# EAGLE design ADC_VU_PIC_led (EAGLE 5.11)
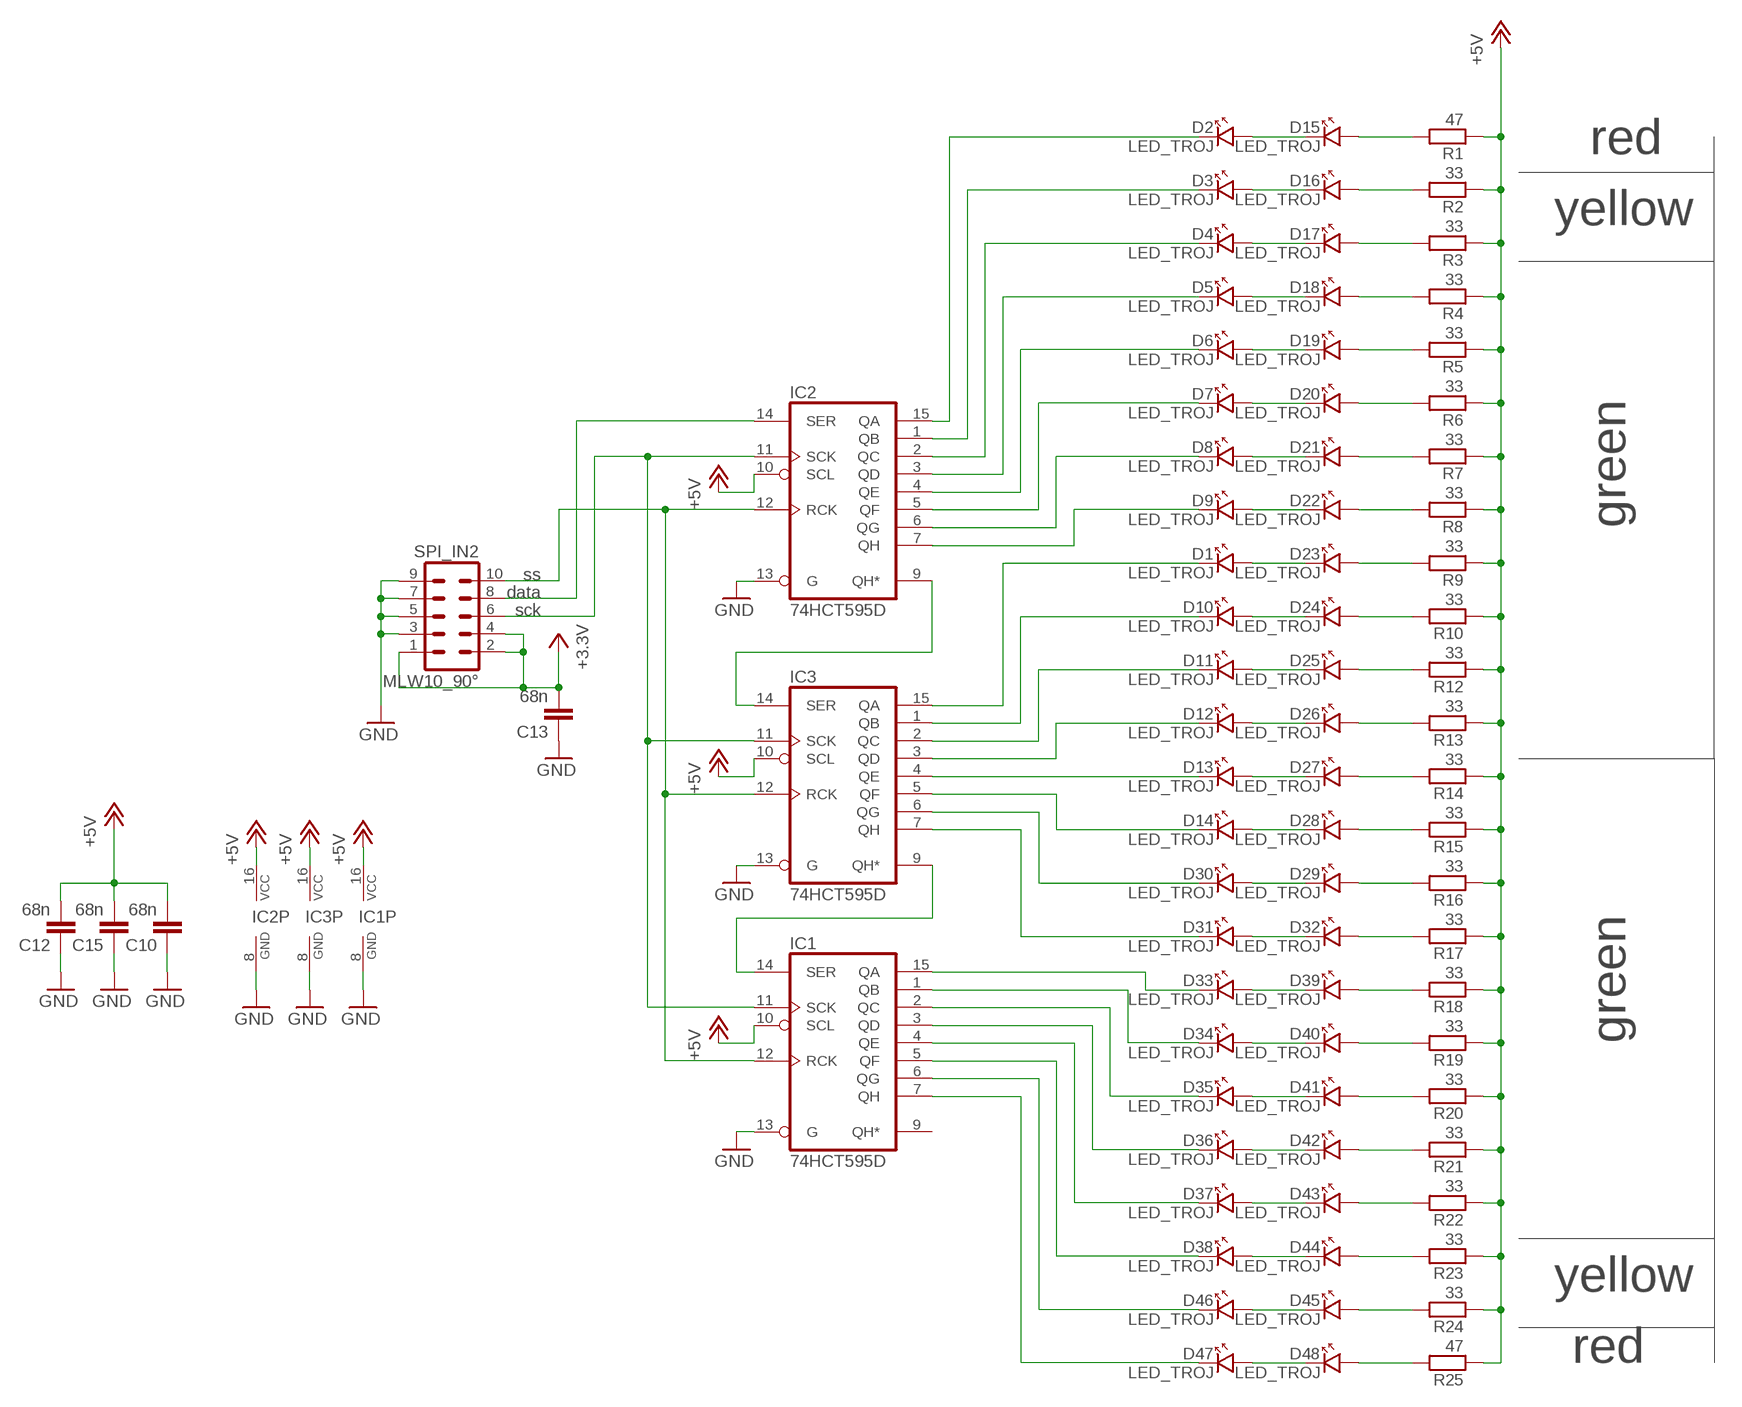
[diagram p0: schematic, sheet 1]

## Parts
C10  68n  C-EUC1206  [C1206]
C12  68n  C-EUC1206  [C1206]
C13  68n  C-EUC1206  [C1206]
C15  68n  C-EUC1206  [C1206]
D1  LED_TROJ  [LED_TROJ]
D2  LED_TROJ  [LED_TROJ]
D3  LED_TROJ  [LED_TROJ]
D4  LED_TROJ  [LED_TROJ]
D5  LED_TROJ  [LED_TROJ]
D6  LED_TROJ  [LED_TROJ]
D7  LED_TROJ  [LED_TROJ]
D8  LED_TROJ  [LED_TROJ]
D9  LED_TROJ  [LED_TROJ]
D10  LED_TROJ  [LED_TROJ]
D11  LED_TROJ  [LED_TROJ]
D12  LED_TROJ  [LED_TROJ]
D13  LED_TROJ  [LED_TROJ]
D14  LED_TROJ  [LED_TROJ]
D15  LED_TROJ  [LED_TROJ]
D16  LED_TROJ  [LED_TROJ]
D17  LED_TROJ  [LED_TROJ]
D18  LED_TROJ  [LED_TROJ]
D19  LED_TROJ  [LED_TROJ]
D20  LED_TROJ  [LED_TROJ]
D21  LED_TROJ  [LED_TROJ]
D22  LED_TROJ  [LED_TROJ]
D23  LED_TROJ  [LED_TROJ]
D24  LED_TROJ  [LED_TROJ]
D25  LED_TROJ  [LED_TROJ]
D26  LED_TROJ  [LED_TROJ]
D27  LED_TROJ  [LED_TROJ]
D28  LED_TROJ  [LED_TROJ]
D29  LED_TROJ  [LED_TROJ]
D30  LED_TROJ  [LED_TROJ]
D31  LED_TROJ  [LED_TROJ]
D32  LED_TROJ  [LED_TROJ]
D33  LED_TROJ  [LED_TROJ]
D34  LED_TROJ  [LED_TROJ]
D35  LED_TROJ  [LED_TROJ]
D36  LED_TROJ  [LED_TROJ]
D37  LED_TROJ  [LED_TROJ]
D38  LED_TROJ  [LED_TROJ]
D39  LED_TROJ  [LED_TROJ]
D40  LED_TROJ  [LED_TROJ]
D41  LED_TROJ  [LED_TROJ]
D42  LED_TROJ  [LED_TROJ]
D43  LED_TROJ  [LED_TROJ]
D44  LED_TROJ  [LED_TROJ]
D45  LED_TROJ  [LED_TROJ]
D46  LED_TROJ  [LED_TROJ]
D47  LED_TROJ  [LED_TROJ]
D48  LED_TROJ  [LED_TROJ]
IC1  74HCT595D  [SO16]
IC2  74HCT595D  [SO16]
IC3  74HCT595D  [SO16]
R1  47  R_SMD_0805  [0805]
R2  33  R_SMD_0805  [0805]
R3  33  R_SMD_0805  [0805]
R4  33  R_SMD_0805  [0805]
R5  33  R_SMD_0805  [0805]
R6  33  R_SMD_0805  [0805]
R7  33  R_SMD_0805  [0805]
R8  33  R_SMD_0805  [0805]
R9  33  R_SMD_0805  [0805]
R10  33  R_SMD_0805  [0805]
R12  33  R_SMD_0805  [0805]
R13  33  R_SMD_0805  [0805]
R14  33  R_SMD_0805  [0805]
R15  33  R_SMD_0805  [0805]
R16  33  R_SMD_0805  [0805]
R17  33  R_SMD_0805  [0805]
R18  33  R_SMD_0805  [0805]
R19  33  R_SMD_0805  [0805]
R20  33  R_SMD_0805  [0805]
R21  33  R_SMD_0805  [0805]
R22  33  R_SMD_0805  [0805]
R23  33  R_SMD_0805  [0805]
R24  33  R_SMD_0805  [0805]
R25  47  R_SMD_0805  [0805]
SPI_IN2  MLW10_90°  [MLW10A]

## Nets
+12V: C10.2 C12.2 C15.2 IC1.10(SCL) IC1.16(VCC) IC2.10(SCL) IC2.16(VCC) IC3.10(SCL) IC3.16(VCC) R1.1 R2.1 R3.1 R4.1 R5.1 R6.1 R7.1 R8.1 R9.1 R10.1 R12.1 R13.1 R14.1 R15.1 R16.1 R17.1 R18.1 R19.1 R20.1 R21.1 R22.1 R23.1 R24.1 R25.1 ; supply symbol labelled +5V
GND: C10.1 C12.1 C13.1 C15.1 IC1.8(GND) IC1.13(G) IC2.8(GND) IC2.13(G) IC3.8(GND) IC3.13(G) SPI_IN2.3 SPI_IN2.5 SPI_IN2.7 SPI_IN2.9
N$1: IC1.14(SER) IC3.9(QH*)
N$2: D31.K IC3.7(QH)
N$3: D2.A D15.K
N$4: D3.A D16.K
N$5: D4.A D17.K
N$6: D5.A D18.K
N$7: D6.A D19.K
N$8: D7.A D20.K
N$9: D8.A D21.K
N$10: D9.A D22.K
N$11: D33.K IC1.15(QA)
N$12: D46.K IC1.6(QG)
N$13: D34.K IC1.1(QB)
N$14: D1.A D23.K
N$15: D35.K IC1.2(QC)
N$16: IC1.11(SCK) IC2.11(SCK) IC3.11(SCK) SPI_IN2.6
N$17: D36.K IC1.3(QD)
N$18: D37.K IC1.4(QE)
N$19: D38.K IC1.5(QF)
N$20: D2.K IC2.15(QA)
N$21: D3.K IC2.1(QB)
N$22: D9.K IC2.7(QH)
N$23: D10.A D24.K
N$24: D11.A D25.K
N$25: D12.A D26.K
N$26: D13.A D27.K
N$27: D14.A D28.K
N$28: D29.K D30.A
N$29: D31.A D32.K
N$30: D33.A D39.K
N$31: D34.A D40.K
N$32: D35.A D41.K
N$33: D36.A D42.K
N$34: D37.A D43.K
N$35: D38.A D44.K
N$36: D4.K IC2.2(QC)
N$37: D5.K IC2.3(QD)
N$38: D8.K IC2.6(QG)
N$39: D7.K IC2.5(QF)
N$40: D6.K IC2.4(QE)
N$41: D45.K D46.A
N$42: D1.K IC3.15(QA)
N$43: D30.K IC3.6(QG)
N$44: D10.K IC3.1(QB)
N$45: D11.K IC3.2(QC)
N$46: D12.K IC3.3(QD)
N$47: D47.A D48.K
N$48: D14.K IC3.5(QF)
N$49: D47.K IC1.7(QH)
N$50: IC2.14(SER) SPI_IN2.8
N$51: D15.A R1.2
N$52: IC2.9(QH*) IC3.14(SER)
N$53: IC1.12(RCK) IC2.12(RCK) IC3.12(RCK) SPI_IN2.10
N$55: D16.A R2.2
N$56: D17.A R3.2
N$57: C13.2 SPI_IN2.1 SPI_IN2.2 SPI_IN2.4 ; supply symbol labelled +3.3V
N$58: D18.A R4.2
N$63: D19.A R5.2
N$64: D20.A R6.2
N$65: D21.A R7.2
N$66: D22.A R8.2
N$67: D23.A R9.2
N$68: D24.A R10.2
N$69: D25.A R12.2
N$70: D26.A R13.2
N$71: D27.A R14.2
N$72: D28.A R15.2
N$73: D29.A R16.2
N$74: D32.A R17.2
N$75: D39.A R18.2
N$76: D40.A R19.2
N$77: D41.A R20.2
N$78: D42.A R21.2
N$79: D43.A R22.2
N$80: D44.A R23.2
N$81: D45.A R24.2
N$82: D48.A R25.2
N$83: D13.K IC3.4(QE)
Unconnected: IC1.9(QH*)

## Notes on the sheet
- red
- yellow
- green
- ss
- data
- sck
- green
- yellow
- red

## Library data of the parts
C10 C12 C13 C15 = rcl:C-EU: CAPACITOR, European symbol
D1-D48 = #PaJa_22:LED: LED - jednobarevna
IC1-IC3 = 74xx-eu:74*595: 8-bit SHIFT REGISTER, output latch
R1-R10 R12-R25 = #PaJa_21:R: Rezistor
SPI_IN2 = #PaJa_21:MLW10: Konektory MLW - vidlice - 10x

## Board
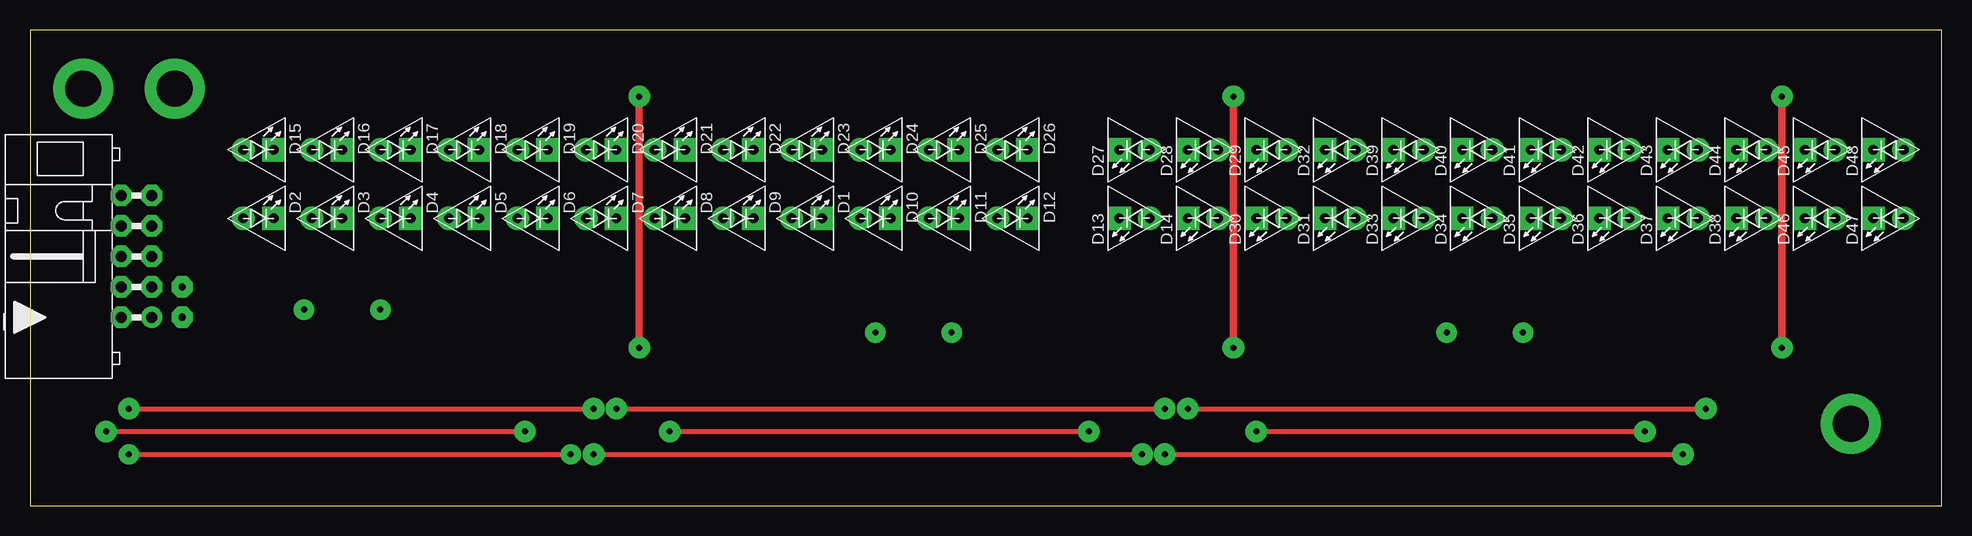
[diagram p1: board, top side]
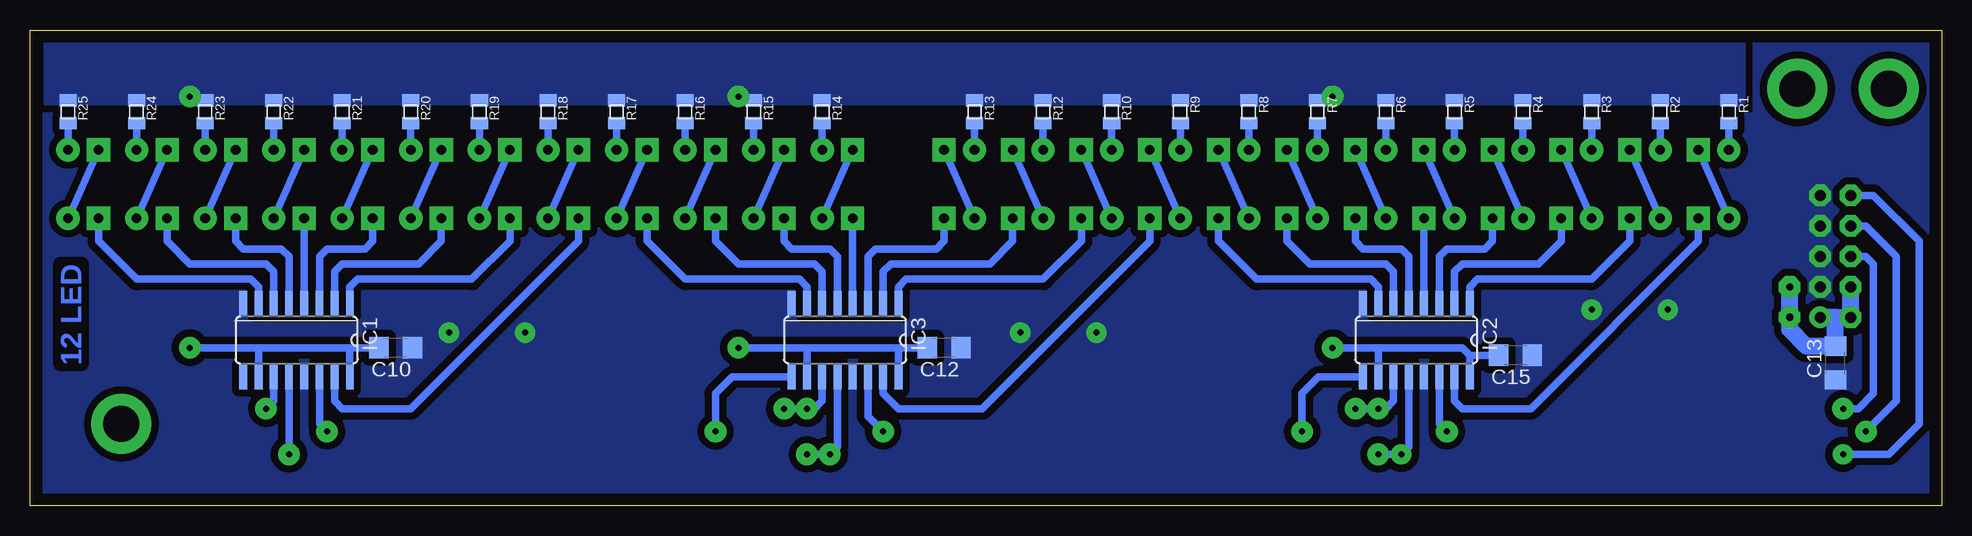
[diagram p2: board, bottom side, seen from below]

Size 159.37 x 39.68 mm. Coordinates in mm from the lower left corner, seen from the top.
Outline: 159.37,39.68 0,39.68 0,0 159.37,0 159.37,39.68
Copper layers (1*16): Top 0.035mm / dielectric 1.5mm / Bottom 0.035mm
Design rules "default *": minimum track width 10mil, minimum drill 24mil, track to track 0.23mm, track to pad 0.23mm, pad to pad 8mil, via to via 8mil, smd to smd 8mil, copper to edge 40mil, drill to drill 8mil, minimum pad ring 10mil, minimum via ring 8mil, stop-mask expansion 4mil, vias tented up to drill 0mil, thermal gap 10mil

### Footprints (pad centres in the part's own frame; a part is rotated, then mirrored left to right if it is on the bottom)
C1206 = smd 1.6 x 1.8: 1 -1.4,0; 2 1.4,0
LED_TROJ = drill 0.813 pad 1.93 round: A -2.54,0 | drill 0.813 pad 1.93 square: K 0,0
SO16 = smd 0.66 x 2.032: 1 -4.445,-3.073; 2 -3.175,-3.073; 3 -1.905,-3.073; 4 -0.635,-3.073; 5 0.635,-3.073; 6 1.905,-3.073; 7 3.175,-3.073; 8 4.445,-3.073; 9 4.445,3.073; 10 3.175,3.073; 11 1.905,3.073; 12 0.635,3.073; 13 -0.635,3.073; 14 -1.905,3.073; 15 -3.175,3.073; 16 -4.445,3.073
0805 = smd 1.016 x 1.422: 1 -0.953,0; 2 0.953,0
MLW10A = drill 0.914 pad 1.778 round: 1 -5.08,-1.27 | drill 0.914 pad 1.778 octagon: 2 -5.08,1.27; 3 -2.54,-1.27; 4 -2.54,1.27; 5 0,-1.27; 6 0,1.27; 7 2.54,-1.27; 8 2.54,1.27; 9 5.08,-1.27; 10 5.08,1.27

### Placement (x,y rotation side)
C10  128.89,13.17 180 bottom
C12  83.17,13.17 180 bottom
C13  8.88,11.9 90 bottom
C15  35.55,12.54 180 bottom
D1  66.03,23.96 0 top
D2  20.3,23.96 0 top
D3  26.02,23.96 0 top
D4  31.73,23.96 0 top
D5  37.45,23.96 0 top
D6  43.16,23.96 0 top
D7  48.88,23.96 0 top
D8  54.59,23.96 0 top
D9  60.31,23.96 0 top
D10  71.74,23.96 0 top
D11  77.45,23.96 0 top
D12  83.17,23.96 0 top
D13  90.79,23.96 180 top
D14  96.5,23.96 180 top
D15  20.3,29.68 0 top
D16  26.02,29.68 0 top
D17  31.73,29.68 0 top
D18  37.45,29.68 0 top
D19  43.16,29.68 0 top
D20  48.88,29.68 0 top
D21  54.59,29.68 0 top
D22  60.31,29.68 0 top
D23  66.03,29.68 0 top
D24  71.74,29.68 0 top
D25  77.45,29.68 0 top
D26  83.17,29.68 0 top
D27  90.79,29.68 180 top
D28  96.5,29.68 180 top
D29  102.22,29.68 180 top
D30  102.22,23.96 180 top
D31  107.94,23.96 180 top
D32  107.94,29.68 180 top
D33  113.65,23.96 180 top
D34  119.36,23.96 180 top
D35  125.08,23.96 180 top
D36  130.8,23.96 180 top
D37  136.51,23.96 180 top
D38  142.23,23.96 180 top
D39  113.65,29.68 180 top
D40  119.36,29.68 180 top
D41  125.08,29.68 180 top
D42  130.8,29.68 180 top
D43  136.51,29.68 180 top
D44  142.23,29.68 180 top
D45  147.94,29.68 180 top
D46  147.94,23.96 180 top
D47  153.66,23.96 180 top
D48  153.66,29.68 180 top
IC1  137.15,13.81 180 bottom
IC2  43.8,13.81 180 bottom
IC3  91.42,13.81 180 bottom
R1  17.77,32.86 270 bottom
R2  23.48,32.86 270 bottom
R3  29.2,32.86 270 bottom
R4  34.91,32.86 270 bottom
R5  40.62,32.86 270 bottom
R6  46.34,32.86 270 bottom
R7  52.05,32.86 270 bottom
R8  57.77,32.86 270 bottom
R9  63.48,32.86 270 bottom
R10  69.2,32.86 270 bottom
R12  74.92,32.86 270 bottom
R13  80.63,32.86 270 bottom
R14  93.33,32.86 270 bottom
R15  99.05,32.86 270 bottom
R16  104.76,32.86 270 bottom
R17  110.47,32.86 270 bottom
R18  116.19,32.86 270 bottom
R19  121.91,32.86 270 bottom
R20  127.62,32.86 270 bottom
R21  133.34,32.86 270 bottom
R22  139.05,32.86 270 bottom
R23  144.77,32.86 270 bottom
R24  150.48,32.86 270 bottom
R25  156.2,32.86 270 bottom
SPI_IN2  8.88,20.79 90 top

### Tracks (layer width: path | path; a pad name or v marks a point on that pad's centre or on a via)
+12V  (via drill 0.5 pad 1.8)
  Top 0.61: v100.31,13.17 v100.31,34.12 | v50.78,13.17 v50.78,34.12 | v146.04,13.17 v146.04,34.12
  Bottom 0.61: 39.35,12.54 IC2.16 | 39.35,12.54 39.99,13.17 46.98,13.17 | 46.98,13.17 v50.78,13.17 | 46.98,13.17 IC2.10 | 86.98,13.17 IC3.16 | 86.98,13.17 94.6,13.17 | 94.6,13.17 IC3.10 | 132.7,13.17 IC1.16 | 132.7,13.17 140.32,13.17 | 140.32,13.17 IC1.10 | 94.6,13.17 v100.31,13.17 | 140.32,13.17 v146.04,13.17 | C10.2 132.7,13.17 | C12.2 86.98,13.17 | C15.2 39.35,12.54
  pour Bottom (isolate 0.61, no thermals): 16.5,33.49 158.1,33.49 158.1,40.48 16.5,40.48
GND  (via drill 0.5 pad 1.7)
  other vias: 124.44,14.44 118.09,14.44 76.82,14.44 70.47,14.44 29.2,16.35 22.84,16.35
  pour Bottom (isolate 0.61, rank 6, no thermals): 160.01,-0.8 -0.65,-0.8 -0.65,40.48 160.01,40.48
N$1  (via drill 0.5 pad 1.8)
  Top 0.406: v102.22,6.18 v134.61,6.18
  Bottom 0.61: IC3.9 100.85,10.73 102.22,9.36 v102.22,6.18 | IC1.14 135.24,6.82 v134.61,6.18
N$2
  Bottom 0.61: IC3.7 94.6,18.25 95.23,18.89 104.76,18.89 107.94,22.06 D31.K
N$3
  Bottom 0.61: D2.A D15.K
N$4
  Bottom 0.61: D3.A D16.K
N$5
  Bottom 0.61: D4.A D17.K
N$6
  Bottom 0.61: D5.A D18.K
N$7
  Bottom 0.61: D6.A D19.K
N$8
  Bottom 0.61: D7.A D20.K
N$9
  Bottom 0.61: D8.A D21.K
N$10
  Bottom 0.61: D9.A D22.K
N$11
  Bottom 0.61: IC1.15 133.97,8.73 133.34,8.09 127.62,8.09 113.65,22.06 D33.K
N$12
  Bottom 0.61: IC1.6 139.05,19.52 139.69,20.16 146.04,20.16 147.94,22.06 D46.K
N$13
  Bottom 0.61: IC1.1 132.7,18.25 132.07,18.89 122.54,18.89 119.36,22.06 D34.K
N$14
  Bottom 0.61: D1.A D23.K
N$15
  Bottom 0.61: IC1.2 133.97,19.52 133.34,20.16 126.98,20.16 125.08,22.06 D35.K
N$16  (via drill 0.5 pad 1.8)
  Top 0.406: v8.24,8.09 v46.98,8.09 | v48.88,8.09 v94.6,8.09 | v96.5,8.09 v139.69,8.09
  Bottom 0.61: SPI_IN2.6 6.33,20.79 5.7,20.16 5.7,9.36 6.97,8.09 v8.24,8.09 | v48.88,8.09 v46.98,8.09 46.34,8.09 45.7,8.73 IC2.11 | v96.5,8.09 v94.6,8.09 93.97,8.09 93.33,8.73 IC3.11 | v139.69,8.09 139.05,8.73 IC1.11
N$17
  Bottom 0.61: IC1.3 135.24,20.79 134.61,21.43 131.43,21.43 130.8,22.06 D36.K
N$18
  Bottom 0.61: IC1.4 D37.K
N$19
  Bottom 0.61: IC1.5 137.78,20.79 138.42,21.43 141.59,21.43 142.23,22.06 D38.K
N$20
  Bottom 0.61: IC2.15 40.62,8.73 39.99,8.09 34.27,8.09 20.3,22.06 D2.K
N$21
  Bottom 0.61: IC2.1 39.35,18.25 38.72,18.89 29.2,18.89 26.02,22.06 D3.K
N$22
  Bottom 0.61: IC2.7 46.98,18.25 47.61,18.89 57.13,18.89 60.31,22.06 D9.K
N$23
  Bottom 0.61: D10.A D24.K
N$24
  Bottom 0.61: D11.A D25.K
N$25
  Bottom 0.61: D12.A D26.K
N$26
  Bottom 0.61: D13.A D27.K
N$27
  Bottom 0.61: D14.A D28.K
N$28
  Bottom 0.61: D30.A D29.K
N$29
  Bottom 0.61: D31.A D32.K
N$30
  Bottom 0.61: D33.A D39.K
N$31
  Bottom 0.61: D34.A D40.K
N$32
  Bottom 0.61: D35.A D41.K
N$33
  Bottom 0.61: D36.A D42.K
N$34
  Bottom 0.61: D37.A D43.K
N$35
  Bottom 0.61: D38.A D44.K
N$36
  Bottom 0.61: IC2.2 40.62,19.52 39.99,20.16 33.64,20.16 31.73,22.06 D4.K
N$37
  Bottom 0.61: IC2.3 41.89,20.79 41.26,21.43 38.09,21.43 37.45,22.06 D5.K
N$38
  Bottom 0.61: IC2.6 45.7,19.52 46.34,20.16 52.69,20.16 54.59,22.06 D8.K
N$39
  Bottom 0.61: IC2.5 44.44,20.79 45.07,21.43 48.24,21.43 48.88,22.06 D7.K
N$40
  Bottom 0.61: IC2.4 D6.K
N$41
  Bottom 0.61: D46.A D45.K
N$42
  Bottom 0.61: IC3.15 88.25,9.36 86.98,8.09 80,8.09 66.03,22.06 D1.K
N$43
  Bottom 0.61: IC3.6 93.33,19.52 93.97,20.16 100.31,20.16 102.22,22.06 D30.K
N$44
  Bottom 0.61: IC3.1 86.98,18.25 86.34,18.89 74.92,18.89 71.74,22.06 D10.K
N$45
  Bottom 0.61: IC3.2 88.25,19.52 87.61,20.16 79.36,20.16 77.45,22.06 D11.K
N$46
  Bottom 0.61: IC3.3 89.52,20.79 88.89,21.43 83.8,21.43 83.17,22.06 D12.K
N$47
  Bottom 0.61: D47.A D48.K
N$48
  Bottom 0.61: IC3.5 92.06,20.79 92.69,21.43 95.87,21.43 96.5,22.06 D14.K
N$49
  Bottom 0.61: IC1.7 140.32,18.25 140.96,18.89 150.48,18.89 153.66,22.06 D47.K
N$50  (via drill 0.5 pad 1.8)
  Top 0.406: v6.33,6.18 v41.26,6.18
  Bottom 0.61: SPI_IN2.8 6.33,23.33 3.79,20.79 3.79,8.73 v6.33,6.18 | v41.26,6.18 41.89,6.82 IC2.14
N$51
  Bottom 0.61: D15.A R1.2
N$52  (via drill 0.5 pad 1.8)
  Top 0.406: v53.33,6.18 v88.25,6.18
  Bottom 0.61: IC3.14 89.52,7.46 v88.25,6.18 | IC2.9 51.95,10.73 53.33,9.36 v53.33,6.18
N$53  (via drill 0.5 pad 1.7, 0.5 pad 1.8)
  Top 0.406: v94.6,4.28 v137.78,4.28 | v46.98,4.28 v92.69,4.28 | v8.24,4.28 v45.07,4.28
  Bottom 0.61: v94.6,4.28 v92.69,4.28 92.06,4.92 IC3.12 | v137.78,4.28 IC1.12 | SPI_IN2.10 5.7,25.87 1.89,22.06 1.89,6.82 4.43,4.28 v8.24,4.28 | IC2.12 44.44,4.92 v45.07,4.28 v46.98,4.28
N$55
  Bottom 0.61: D16.A R2.2
N$56
  Bottom 0.61: D17.A R3.2
N$57  (via drill 0.6 pad 1.78)
  Bottom 1.422: v12.68,18.25 v12.68,15.71 12.68,14.7 11.29,13.3 C13.2 8.88,15.71 | SPI_IN2.4 SPI_IN2.2 8.88,15.71 | 8.88,15.71 SPI_IN2.1
N$58
  Bottom 0.61: D18.A R4.2
N$63
  Bottom 0.61: D19.A R5.2
N$64
  Bottom 0.61: D20.A R6.2
N$65
  Bottom 0.61: D21.A R7.2
N$66
  Bottom 0.61: D22.A R8.2
N$67
  Bottom 0.61: D23.A R9.2
N$68
  Bottom 0.61: D24.A R10.2
N$69
  Bottom 0.61: D25.A R12.2
N$70
  Bottom 0.61: D26.A R13.2
N$71
  Bottom 0.61: D27.A R14.2
N$72
  Bottom 0.61: D28.A R15.2
N$73
  Bottom 0.61: D29.A R16.2
N$74
  Bottom 0.61: D32.A R17.2
N$75
  Bottom 0.61: D39.A R18.2
N$76
  Bottom 0.61: D40.A R19.2
N$77
  Bottom 0.61: D41.A R20.2
N$78
  Bottom 0.61: D42.A R21.2
N$79
  Bottom 0.61: D43.A R22.2
N$80
  Bottom 0.61: D44.A R23.2
N$81
  Bottom 0.61: D45.A R24.2
N$82
  Bottom 0.61: D48.A R25.2
N$83
  Bottom 0.61: IC3.4 D13.K
N$84  (via drill 3 pad 5)
  other vias: 151.75,6.82
N$85  (via drill 3 pad 5)
  other vias: 4.43,34.76
N$87  (via drill 3 pad 5)
  other vias: 12.05,34.76

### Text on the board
Bottom: 12 LED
